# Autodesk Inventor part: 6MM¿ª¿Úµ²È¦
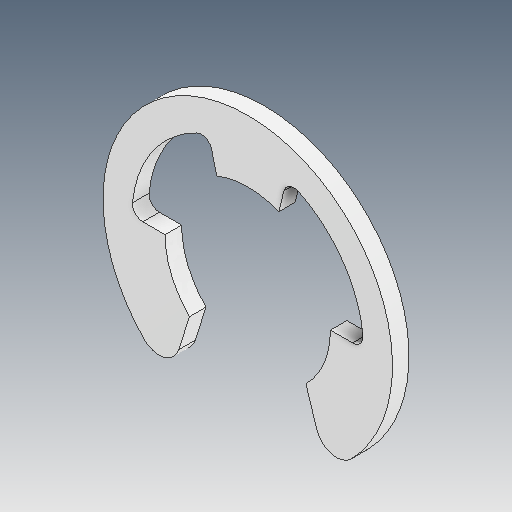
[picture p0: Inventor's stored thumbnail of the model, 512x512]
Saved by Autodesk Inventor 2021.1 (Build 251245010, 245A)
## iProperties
Created: 2021-05
Part Number: 6MM¿ª¿Úµ²È¦
Material: Ogólny
Document SubType Name: Modeling
Designer: user
Density: 1 g/cm^3
Appearance: Domyślna
Author: user
Revision Number: ÈÎºÎ
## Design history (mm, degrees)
feature "ÊäÈë1"
node "Bryła1"
